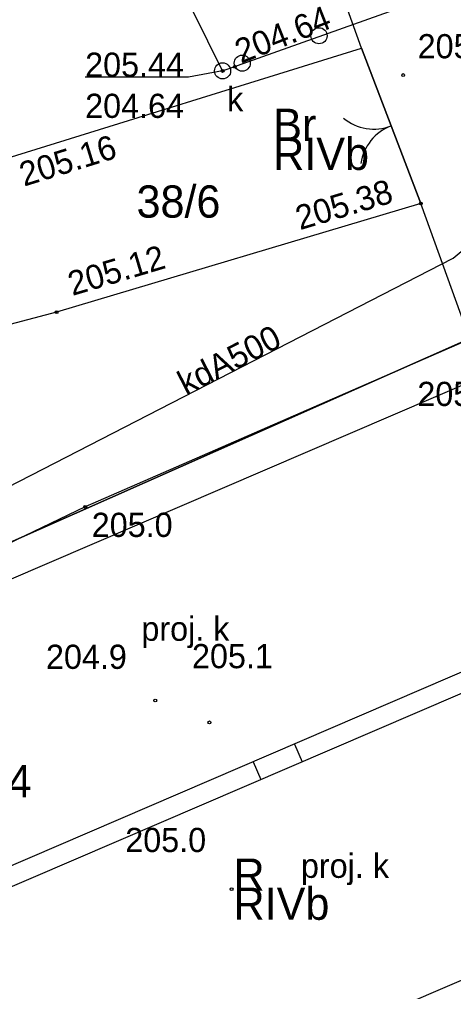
# Model space of a CAD drawing. Extents: x 6512400 to 6513200, y 6022500 to 6022750.
# Drawn here: x 6512825.93 to 6512839.39, y 6022578.54 to 6022608.68 of the extents above; entities that cross this region are included whole.
import ezdxf

# ---------------------------------------------------------------- set-up
doc = ezdxf.new("R2010")
doc.units = 0
for name, color, linetype in [('209-oznaczenie konturu klasyfikacyjnego', 7, 'Continuous'), ('210-oznaczenie konturu użytku gruntowego', 7, 'Continuous'), ('211-numer działki ewidencyjnej', 7, 'Continuous'), ('217-kontur klasyfikacyjny', 7, 'Continuous'), ('218-kontur użytku gruntowego', 7, 'Continuous'), ('219-działka ewidencyjna', 7, 'Continuous'), ('brama', 7, 'Continuous'), ('obszar utwardzony', 7, 'Continuous'), ('ogrodzenie trwałe', 7, 'Continuous'), ('pikieta naturalna', 7, 'Continuous'), ('pikieta naturalna-Atr2', 7, 'Continuous'), ('pikieta sztuczna', 7, 'Continuous'), ('pikieta sztuczna-Atr2', 7, 'Continuous'), ('podpora związana z budynkiem (punkt)', 7, 'Continuous'), ('przewód kanalizacyjny', 7, 'Continuous'), ('przewód kanalizacyjny (linia)', 7, 'Continuous'), ('przewód kanalizacyjny-Atr1', 7, 'Continuous'), ('punkt o określonej wysokości (sieć kanalizacyjna)', 7, 'Continuous'), ('punkt o określonej wysokości (sieć kanalizacyjna)-Atr2', 7, 'Continuous'), ('punkt o określonej wysokości (sieć kanalizacyjna)-Atr3', 7, 'Continuous'), ('punkt wysokościowy naturalny', 7, 'Continuous'), ('punkt wysokościowy naturalny-Atr2', 7, 'Continuous'), ('urządzenie techniczne projektowane lub w budowie (sieć kanalizacyjna) - powierzchnia - ob. projektowany', 7, 'Continuous'), ('urządzenie techniczne projektowane lub w budowie (sieć kanalizacyjna) - powierzchnia - ob. projektowany-Atr17', 7, 'Continuous'), ('właz okrągły - siec kanalizacyjna (punkt)', 7, 'Continuous'), ('właz okrągły - siec kanalizacyjna (punkt)-Atr17', 7, 'Continuous')]:
    doc.layers.add(name, color=color, linetype=linetype)

# ---------------------------------------------------------------- blocks, each defined once
blk = doc.blocks.new('PW01')
blk.add_circle((0, 0), 0.045)
blk = doc.blocks.new('US22')
blk.add_circle((0, 0), 0.25)
blk = doc.blocks.new('OK02')
for centre, start, end in [((-1.5, 0), 0, 60), ((1.5, 0), 120, 180)]:
    blk.add_arc(centre, 1.5, start, end)
blk = doc.blocks.new('IB04')
blk.add_circle((0, 0), 0.25)

msp = doc.modelspace()

# ---------------------------------------------------------------- linework, layer by layer
at = {"layer": '217-kontur klasyfikacyjny'}
for points in [[(6512811.09, 6022586.02), (6512848.55, 6022602.62)], [(6512848.55, 6022602.62), (6512811.09, 6022586.02)]]:
    msp.add_lwpolyline(points, dxfattribs=at)
at = {"layer": '218-kontur użytku gruntowego'}
for points in [[(6512811.09, 6022586.02), (6512848.55, 6022602.62)], [(6512848.55, 6022602.62), (6512811.09, 6022586.02)]]:
    msp.add_lwpolyline(points, dxfattribs=at)
at = {"layer": '219-działka ewidencyjna'}
msp.add_lwpolyline([(6512811.09, 6022586.02), (6512848.55, 6022602.62)], dxfattribs=at)
at = {"layer": 'brama'}
msp.add_lwpolyline([(6512838.38, 6022602.97), (6512836.54, 6022607.78)], dxfattribs=at)
at = {"layer": 'obszar utwardzony'}
msp.add_lwpolyline([(6512812.81, 6022633.6), (6512816.07, 6022632.65), (6512815.94, 6022630.05), (6512811.75, 6022615.46), (6512809.03, 6022605.91), (6512807.28, 6022599.67), (6512817.34, 6022602.22), (6512825.55, 6022604.37), (6512836.54, 6022607.78), (6512838.38, 6022602.97), (6512827.08, 6022599.6), (6512818.35, 6022597.29), (6512807.91, 6022594.59), (6512801.11, 6022596.47), (6512802.38, 6022600.88), (6512804.17, 6022607.14), (6512806.87, 6022616.66), (6512807.12, 6022617.53), (6512808.57, 6022622.5), (6512808.8, 6022623.37), (6512810.76, 6022630.26), (6512810.85, 6022630.66), (6512811.87, 6022630.4), (6512812.08, 6022631.12)], close=True, dxfattribs=at)
at = {"layer": 'ogrodzenie trwałe'}
for points in [[(6512836.54, 6022607.78), (6512835.06, 6022611.91)], [(6512847.46, 6022602.32), (6512839.9, 6022598.76), (6512838.38, 6022602.97)], [(6512839.9, 6022598.76), (6512827.97, 6022593.56), (6512815.03, 6022587.35), (6512805.68, 6022582.71), (6512799.86, 6022579.98), (6512797.99, 6022580.48)]]:
    msp.add_lwpolyline(points, dxfattribs=at)
at = {"layer": 'przewód kanalizacyjny'}
msp.add_lwpolyline([(6512821.92, 6022592.3), (6512839.38, 6022601.27), (6512844.43, 6022605.49), (6512845.59, 6022604.41), (6512846.7, 6022605.53), (6512847.74, 6022606.78)], dxfattribs=at)
at = {"layer": 'przewód kanalizacyjny (linia)'}
for points in [[(6512832.23, 6022607.08), (6512824.55, 6022622.58)], [(6512832.23, 6022607.08), (6512853.7, 6022614.72)]]:
    msp.add_lwpolyline(points, dxfattribs=at)
at = {"layer": 'punkt o określonej wysokości (sieć kanalizacyjna)-Atr2'}
msp.add_lwpolyline([(6512832.23, 6022607.08), (6512831.17, 6022606.89), (6512827.966, 6022606.89)], dxfattribs=at)
at = {"layer": 'urządzenie techniczne projektowane lub w budowie (sieć kanalizacyjna) - powierzchnia - ob. projektowany'}
for points in [[(6512813.61, 6022586.15), (6512845.46, 6022599.83)], [(6512848.68, 6022592.32), (6512816.84, 6022578.64)], [(6512817.02, 6022578.07), (6512848.86, 6022591.74)], [(6512834.46, 6022586.21), (6512834.7, 6022585.66)], [(6512833.18, 6022585.66), (6512833.42, 6022585.11)], [(6512852.09, 6022584.23), (6512820.25, 6022570.56)]]:
    msp.add_lwpolyline(points, dxfattribs=at)

# ---------------------------------------------------------------- block references
at = {"layer": 'brama', "rotation": 110.934}
msp.add_blockref('OK02', (6512837.46, 6022605.375), dxfattribs=at)
at = {"layer": 'pikieta naturalna'}
for p in [(6512827.97, 6022593.56), (6512830.14, 6022587.56), (6512832.51, 6022581.71)]:
    msp.add_blockref('PW01', p, dxfattribs=at)
at = {"layer": 'pikieta sztuczna'}
for p in [(6512838.38, 6022602.97), (6512827.08, 6022599.6)]:
    msp.add_blockref('PW01', p, dxfattribs=at)
at = {"layer": 'podpora związana z budynkiem (punkt)'}
for p in [(6512835.22, 6022608.17), (6512832.84, 6022607.32)]:
    msp.add_blockref('IB04', p, dxfattribs=at)
at = {"layer": 'punkt o określonej wysokości (sieć kanalizacyjna)'}
for p in [(6512832.61, 6022607.21), (6512832.23, 6022607.08)]:
    msp.add_blockref('PW01', p, dxfattribs=at)
at = {"layer": 'punkt wysokościowy naturalny'}
for p in [(6512837.83, 6022606.95), (6512831.82, 6022586.88)]:
    msp.add_blockref('PW01', p, dxfattribs=at)
at = {"layer": 'właz okrągły - siec kanalizacyjna (punkt)'}
msp.add_blockref('US22', (6512832.23, 6022607.08), dxfattribs=at)

# ---------------------------------------------------------------- texts
at = {"layer": '209-oznaczenie konturu klasyfikacyjnego'}
for p in [(6512833.8, 6022604.01), (6512832.57, 6022580.76)]:
    msp.add_text('RIVb', height=1, dxfattribs=at).set_placement(p)
at = {"layer": '210-oznaczenie konturu użytku gruntowego'}
for s, p in [('Br', (6512833.8, 6022604.91)), ('R', (6512832.57, 6022581.66))]:
    msp.add_text(s, height=1, dxfattribs=at).set_placement(p)
at = {"layer": '211-numer działki ewidencyjnej'}
for s, p in [('38/6', (6512829.56, 6022602.53)), ('38/4', (6512823.7, 6022584.56))]:
    msp.add_text(s, height=1, dxfattribs=at).set_placement(p)
at = {"layer": 'pikieta naturalna-Atr2'}
for s, p in [('205.4', (6512838.27, 6022596.69)), ('205.0', (6512828.17, 6022592.63)), ('204.9', (6512826.75, 6022588.54)), ('205.0', (6512829.21, 6022582.86))]:
    msp.add_text(s, height=0.75, dxfattribs=at).set_placement(p)
at = {"layer": 'pikieta sztuczna-Atr2'}
for s, rotation, p in [('205.16', 17.238, (6512826.07, 6022603.49)), ('205.38', 16.606, (6512834.63, 6022602.14)), ('205.12', 16.606, (6512827.57, 6022600.1))]:
    msp.add_text(s, height=0.75, rotation=rotation, dxfattribs=at).set_placement(p)
at = {"layer": 'przewód kanalizacyjny-Atr1'}
msp.add_text('kdA500', height=0.75, rotation=27.192, dxfattribs=at).set_placement((6512831.09, 6022597.01))
at = {"layer": 'punkt o określonej wysokości (sieć kanalizacyjna)-Atr2'}
msp.add_text('204.64', height=0.75, rotation=21.531, dxfattribs=at).set_placement((6512832.8, 6022607.3))
msp.add_text('205.44', height=0.75, dxfattribs=at).set_placement((6512827.966, 6022606.897))
at = {"layer": 'punkt o określonej wysokości (sieć kanalizacyjna)-Atr3'}
msp.add_text('204.64', height=0.75, dxfattribs=at).set_placement((6512827.966, 6022605.622))
at = {"layer": 'punkt wysokościowy naturalny-Atr2'}
for s, p in [('205.3', (6512838.28, 6022607.47)), ('205.1', (6512831.28, 6022588.56))]:
    msp.add_text(s, height=0.75, dxfattribs=at).set_placement(p)
at = {"layer": 'urządzenie techniczne projektowane lub w budowie (sieć kanalizacyjna) - powierzchnia - ob. projektowany-Atr17'}
for p in [(6512829.71, 6022589.41), (6512834.66, 6022582.06)]:
    msp.add_text('proj. k', height=0.75, dxfattribs=at).set_placement(p)
at = {"layer": 'właz okrągły - siec kanalizacyjna (punkt)-Atr17'}
msp.add_text('k', height=0.75, dxfattribs=at).set_placement((6512832.37, 6022605.83))

doc.saveas('drawing.dxf')
